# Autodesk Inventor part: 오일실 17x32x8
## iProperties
IsCustomPart: 1
Company: 한국ATC센터
Created: 2014-07
Part Number: 오일실 17x32x8
Material: 고무
Description: 오일-실
Document SubType Name: Modeling
Standard: KS B 2804
Designer: KYOUNG IL JANG
Standards Organization: KS
Language: ko-KR
Size Designation: D - 17 32 8
Categories: <MemberInstance><Categories><Category DisplayName="샤프트 부품" InternalName="7f7aeb1f-a693-4053-b835-cee3144e0d98" Mnemonic="SHFT"><Category DisplayName="실링" Intern
Density: 0.93 g/cm^3
Author: KYOUNG IL JANG
